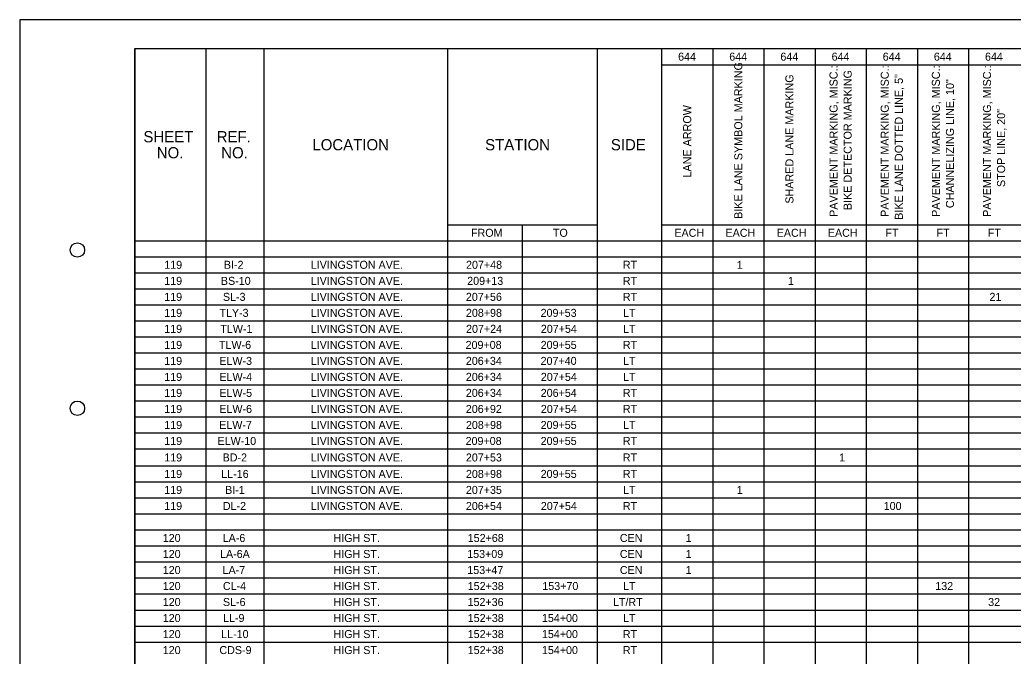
# Model space of a CAD drawing. Extents: x 1822379 to 1824724, y 710341 to 711455.
# Drawn here: x 1822379.11 to 1822396.38, y 711209.81 to 711220.87 of the extents above; entities that cross this region are included whole.
import ezdxf

# ---------------------------------------------------------------- set-up
doc = ezdxf.new("R2010")
doc.units = 0
for name, color, linetype in [('SH_Border', 7, 'Continuous'), ('SH_Cut_Line', 7, 'Continuous'), ('SH_Data', 7, 'Continuous'), ('SH_Text', 7, 'Continuous')]:
    doc.layers.add(name, color=color, linetype=linetype)

msp = doc.modelspace()

# ---------------------------------------------------------------- linework, layer by layer
at = {"layer": 'SH_Border'}
msp.add_lwpolyline([(1822381.113, 711220.366), (1822412.613, 711220.366), (1822412.613, 711199.366), (1822381.113, 711199.366)], close=True, dxfattribs=at)
for centre in [(1822380.113, 711216.866), (1822380.113, 711214.116)]:
    msp.add_circle(centre, 0.125, dxfattribs=at)
at = {"layer": 'SH_Cut_Line'}
msp.add_lwpolyline([(1822379.113, 711198.866), (1822413.113, 711198.866), (1822413.113, 711220.866), (1822379.113, 711220.866)], close=True, dxfattribs=at)
at = {"layer": 'SH_Data'}
for p, q in [((1822381.113, 711220.366), (1822411.613, 711220.366)), ((1822381.113, 711220.366), (1822381.113, 711199.333)), ((1822382.348, 711220.366), (1822382.348, 711201.575)), ((1822383.352, 711220.366), (1822383.352, 711201.575)), ((1822386.547, 711220.366), (1822386.547, 711201.575)), ((1822389.149, 711220.366), (1822389.149, 711201.575)), ((1822390.269, 711220.366), (1822390.269, 711199.333)), ((1822391.158, 711220.366), (1822391.158, 711199.333)), ((1822392.048, 711220.366), (1822392.048, 711199.333)), ((1822392.937, 711220.366), (1822392.937, 711199.333)), ((1822393.826, 711220.366), (1822393.826, 711199.333)), ((1822394.716, 711220.366), (1822394.716, 711199.333)), ((1822395.605, 711220.366), (1822395.605, 711199.333)), ((1822390.269, 711220.087), (1822411.613, 711220.087)), ((1822386.547, 711217.305), (1822389.149, 711217.305)), ((1822387.848, 711217.305), (1822387.848, 711201.575)), ((1822390.269, 711217.305), (1822411.613, 711217.305)), ((1822381.113, 711217.027), (1822411.613, 711217.027)), ((1822381.113, 711216.748), (1822411.613, 711216.748)), ((1822381.113, 711216.47), (1822411.613, 711216.47)), ((1822381.113, 711216.192), (1822411.613, 711216.192)), ((1822381.113, 711215.913), (1822411.613, 711215.913)), ((1822381.113, 711215.635), (1822411.613, 711215.635)), ((1822381.113, 711215.357), (1822411.613, 711215.357)), ((1822381.113, 711215.079), (1822411.613, 711215.079)), ((1822381.113, 711214.8), (1822411.613, 711214.8)), ((1822381.113, 711214.522), (1822411.613, 711214.522)), ((1822381.113, 711214.244), (1822411.613, 711214.244)), ((1822381.113, 711213.966), (1822411.613, 711213.966)), ((1822381.113, 711213.687), (1822411.613, 711213.687)), ((1822381.113, 711213.409), (1822411.613, 711213.409)), ((1822381.113, 711213.115), (1822411.613, 711213.115)), ((1822381.113, 711212.836), (1822411.613, 711212.836)), ((1822381.113, 711212.558), (1822411.613, 711212.558)), ((1822381.113, 711212.28), (1822411.613, 711212.28)), ((1822381.113, 711212.002), (1822411.613, 711212.002)), ((1822381.113, 711211.723), (1822411.613, 711211.723)), ((1822381.113, 711211.445), (1822411.613, 711211.445)), ((1822381.113, 711211.167), (1822411.613, 711211.167)), ((1822381.113, 711210.889), (1822411.613, 711210.889)), ((1822381.113, 711210.61), (1822411.613, 711210.61)), ((1822381.113, 711210.332), (1822411.613, 711210.332)), ((1822381.113, 711210.054), (1822411.613, 711210.054))]:
    msp.add_line(p, q, dxfattribs=at)

# ---------------------------------------------------------------- texts
at = {"layer": 'SH_Text'}
for s, height, p in [('644', 0.1391, (1822390.557, 711220.157)), ('644', 0.1391, (1822391.446, 711220.157)), ('644', 0.1391, (1822392.335, 711220.157)), ('644', 0.1391, (1822393.225, 711220.157)), ('644', 0.1391, (1822394.114, 711220.157)), ('644', 0.1391, (1822395.003, 711220.157)), ('644', 0.1391, (1822395.892, 711220.157)), ('SHEET', 0.1948, (1822381.26, 711218.738)), ('REF.', 0.1948, (1822382.535, 711218.738)), ('LOCATION', 0.1948, (1822384.198, 711218.599)), ('STATION', 0.1948, (1822387.201, 711218.599)), ('SIDE', 0.1948, (1822389.387, 711218.599)), ('NO.', 0.1948, (1822381.493, 711218.46)), ('NO.', 0.1948, (1822382.613, 711218.46)), ('FROM', 0.1391, (1822386.956, 711217.096)), ('TO', 0.1391, (1822388.38, 711217.096)), ('EACH', 0.1391, (1822390.492, 711217.096)), ('EACH', 0.1391, (1822391.381, 711217.096)), ('EACH', 0.1391, (1822392.271, 711217.096)), ('EACH', 0.1391, (1822393.16, 711217.096)), ('FT', 0.1391, (1822394.161, 711217.096)), ('FT', 0.1391, (1822395.05, 711217.096)), ('FT', 0.1391, (1822395.94, 711217.096)), ('119', 0.1391, (1822381.623, 711216.54)), ('BI-2', 0.1391, (1822382.66, 711216.54)), ('LIVINGSTON AVE.', 0.13913, (1822384.17, 711216.54)), ('207+48', 0.1391, (1822386.87, 711216.54)), ('RT', 0.1391, (1822389.596, 711216.54)), ('1', 0.139, (1822391.577, 711216.54)), ('119', 0.1391, (1822381.623, 711216.261)), ('BS-10', 0.1391, (1822382.608, 711216.261)), ('LIVINGSTON AVE.', 0.13913, (1822384.17, 711216.261)), ('209+13', 0.1391, (1822386.89, 711216.261)), ('RT', 0.1391, (1822389.596, 711216.261)), ('1', 0.139, (1822392.466, 711216.261)), ('119', 0.1391, (1822381.623, 711215.983)), ('SL-3', 0.1391, (1822382.643, 711215.983)), ('LIVINGSTON AVE.', 0.13913, (1822384.17, 711215.983)), ('207+56', 0.1391, (1822386.867, 711215.983)), ('RT', 0.1391, (1822389.596, 711215.983)), ('21', 0.1391, (1822395.97, 711215.983)), ('119', 0.1391, (1822381.623, 711215.705)), ('TLY-3', 0.1391, (1822382.582, 711215.705)), ('LIVINGSTON AVE.', 0.13913, (1822384.17, 711215.705)), ('208+98', 0.1391, (1822386.868, 711215.705)), ('209+53', 0.1391, (1822388.166, 711215.705)), ('LT', 0.1391, (1822389.599, 711215.705)), ('119', 0.1391, (1822381.623, 711215.427)), ('TLW-1', 0.1391, (1822382.598, 711215.427)), ('LIVINGSTON AVE.', 0.13913, (1822384.17, 711215.427)), ('207+24', 0.1391, (1822386.87, 711215.427)), ('207+54', 0.1391, (1822388.17, 711215.427)), ('LT', 0.1391, (1822389.599, 711215.427)), ('119', 0.1391, (1822381.623, 711215.148)), ('TLW-6', 0.1391, (1822382.575, 711215.148)), ('LIVINGSTON AVE.', 0.13913, (1822384.17, 711215.148)), ('209+08', 0.1391, (1822386.862, 711215.148)), ('209+55', 0.1391, (1822388.167, 711215.148)), ('RT', 0.1391, (1822389.596, 711215.148)), ('119', 0.1391, (1822381.623, 711214.87)), ('ELW-3', 0.1391, (1822382.58, 711214.87)), ('LIVINGSTON AVE.', 0.13913, (1822384.17, 711214.87)), ('206+34', 0.1391, (1822386.866, 711214.87)), ('207+40', 0.1391, (1822388.166, 711214.87)), ('LT', 0.1391, (1822389.599, 711214.87)), ('119', 0.1391, (1822381.623, 711214.592)), ('LIVINGSTON AVE.', 0.13913, (1822384.17, 711214.592)), ('206+34', 0.1391, (1822386.866, 711214.592)), ('207+54', 0.1391, (1822388.17, 711214.592)), ('ELW-4', 0.1391, (1822382.582, 711214.592)), ('LT', 0.1391, (1822389.599, 711214.592)), ('119', 0.1391, (1822381.623, 711214.314)), ('ELW-5', 0.1391, (1822382.581, 711214.314)), ('LIVINGSTON AVE.', 0.13913, (1822384.17, 711214.314)), ('206+34', 0.1391, (1822386.866, 711214.314)), ('206+54', 0.1391, (1822388.168, 711214.314)), ('RT', 0.1391, (1822389.596, 711214.314)), ('119', 0.1391, (1822381.623, 711214.035)), ('ELW-6', 0.1391, (1822382.58, 711214.035)), ('LIVINGSTON AVE.', 0.13913, (1822384.17, 711214.035)), ('206+92', 0.1391, (1822386.866, 711214.035)), ('207+54', 0.1391, (1822388.17, 711214.035)), ('RT', 0.1391, (1822389.596, 711214.035)), ('119', 0.1391, (1822381.623, 711213.757)), ('ELW-7', 0.1391, (1822382.578, 711213.757)), ('LIVINGSTON AVE.', 0.13913, (1822384.17, 711213.757)), ('208+98', 0.1391, (1822386.868, 711213.757)), ('209+55', 0.1391, (1822388.167, 711213.757)), ('LT', 0.1391, (1822389.599, 711213.757)), ('119', 0.1391, (1822381.623, 711213.479)), ('ELW-10', 0.1391, (1822382.549, 711213.479)), ('LIVINGSTON AVE.', 0.13913, (1822384.17, 711213.479)), ('209+08', 0.1391, (1822386.862, 711213.479)), ('209+55', 0.1391, (1822388.167, 711213.479)), ('RT', 0.1391, (1822389.596, 711213.479)), ('119', 0.1391, (1822381.623, 711213.192)), ('BD-2', 0.1391, (1822382.638, 711213.192)), ('LIVINGSTON AVE.', 0.13913, (1822384.17, 711213.192)), ('207+53', 0.1391, (1822386.867, 711213.192)), ('RT', 0.1391, (1822389.596, 711213.192)), ('1', 0.139, (1822393.356, 711213.192)), ('119', 0.1391, (1822381.623, 711212.906)), ('LL-16', 0.1391, (1822382.614, 711212.906)), ('LIVINGSTON AVE.', 0.13913, (1822384.17, 711212.906)), ('208+98', 0.1391, (1822386.868, 711212.906)), ('209+55', 0.1391, (1822388.167, 711212.906)), ('RT', 0.1391, (1822389.596, 711212.906)), ('119', 0.1391, (1822381.623, 711212.628)), ('BI-1', 0.1391, (1822382.681, 711212.628)), ('LIVINGSTON AVE.', 0.13913, (1822384.17, 711212.628)), ('207+35', 0.1391, (1822386.867, 711212.628)), ('LT', 0.1391, (1822389.599, 711212.628)), ('1', 0.139, (1822391.577, 711212.628)), ('119', 0.1391, (1822381.623, 711212.349)), ('DL-2', 0.1391, (1822382.642, 711212.349)), ('LIVINGSTON AVE.', 0.13913, (1822384.17, 711212.349)), ('206+54', 0.1391, (1822386.867, 711212.349)), ('207+54', 0.1391, (1822388.17, 711212.349)), ('RT', 0.1391, (1822389.596, 711212.349)), ('100', 0.1391, (1822394.131, 711212.349)), ('120', 0.1391, (1822381.597, 711211.793)), ('LA-6', 0.1391, (1822382.639, 711211.793)), ('HIGH ST.', 0.1391, (1822384.566, 711211.793)), ('152+68', 0.1391, (1822386.899, 711211.793)), ('CEN', 0.1391, (1822389.544, 711211.793)), ('1', 0.139, (1822390.688, 711211.793)), ('120', 0.1391, (1822381.597, 711211.515)), ('LA-6A', 0.1391, (1822382.593, 711211.515)), ('HIGH ST.', 0.1391, (1822384.566, 711211.515)), ('153+09', 0.1391, (1822386.89, 711211.515)), ('CEN', 0.1391, (1822389.544, 711211.515)), ('1', 0.139, (1822390.688, 711211.515)), ('120', 0.1391, (1822381.597, 711211.236)), ('LA-7', 0.1391, (1822382.637, 711211.236)), ('HIGH ST.', 0.1391, (1822384.566, 711211.236)), ('153+47', 0.1391, (1822386.892, 711211.236)), ('CEN', 0.1391, (1822389.544, 711211.236)), ('1', 0.139, (1822390.688, 711211.236)), ('120', 0.1391, (1822381.597, 711210.958)), ('CL-4', 0.1391, (1822382.643, 711210.958)), ('HIGH ST.', 0.1391, (1822384.566, 711210.958)), ('152+38', 0.1391, (1822386.899, 711210.958)), ('153+70', 0.1391, (1822388.196, 711210.958)), ('LT', 0.1391, (1822389.599, 711210.958)), ('132', 0.1391, (1822395.028, 711210.958)), ('120', 0.1391, (1822381.597, 711210.68)), ('SL-6', 0.1391, (1822382.643, 711210.68)), ('HIGH ST.', 0.1391, (1822384.566, 711210.68)), ('152+36', 0.1391, (1822386.896, 711210.68)), ('LT/RT', 0.1391, (1822389.424, 711210.68)), ('32', 0.1391, (1822395.947, 711210.68)), ('120', 0.1391, (1822381.597, 711210.402)), ('LL-9', 0.1391, (1822382.645, 711210.402)), ('HIGH ST.', 0.1391, (1822384.566, 711210.402)), ('152+38', 0.1391, (1822386.899, 711210.402)), ('154+00', 0.1391, (1822388.189, 711210.402)), ('LT', 0.1391, (1822389.599, 711210.402)), ('120', 0.1391, (1822381.597, 711210.123)), ('LL-10', 0.1391, (1822382.613, 711210.123)), ('HIGH ST.', 0.1391, (1822384.566, 711210.123)), ('152+38', 0.1391, (1822386.899, 711210.123)), ('154+00', 0.1391, (1822388.189, 711210.123)), ('RT', 0.1391, (1822389.596, 711210.123)), ('120', 0.1391, (1822381.597, 711209.845)), ('CDS-9', 0.1391, (1822382.582, 711209.845)), ('HIGH ST.', 0.1391, (1822384.566, 711209.845)), ('152+38', 0.1391, (1822386.899, 711209.845)), ('154+00', 0.1391, (1822388.189, 711209.845)), ('RT', 0.1391, (1822389.596, 711209.845))]:
    msp.add_text(s, height=height, dxfattribs=at).set_placement(p)
for s, height, p in [('BIKE LANE SYMBOL MARKING', 0.13998, (1822391.673, 711217.407)), ('PAVEMENT MARKING, MISC.:', 0.13998, (1822393.329, 711217.442)), ('BIKE DETECTOR MARKING', 0.13998, (1822393.574, 711217.56)), ('PAVEMENT MARKING, MISC.:', 0.13998, (1822394.219, 711217.442)), ('BIKE LANE DOTTED LINE, 5"', 0.13998, (1822394.464, 711217.392)), ('PAVEMENT MARKING, MISC.:', 0.13998, (1822395.108, 711217.442)), ('PAVEMENT MARKING, MISC.:', 0.13998, (1822395.997, 711217.442)), ('SHARED LANE MARKING', 0.13998, (1822392.562, 711217.672)), ('CHANNELIZING LINE, 10"', 0.13998, (1822395.353, 711217.594)), ('LANE ARROW', 0.14, (1822390.784, 711218.126)), ('STOP LINE, 20"', 0.13998, (1822396.242, 711217.96))]:
    msp.add_text(s, height=height, rotation=90, dxfattribs=at).set_placement(p)

doc.saveas('drawing.dxf')
